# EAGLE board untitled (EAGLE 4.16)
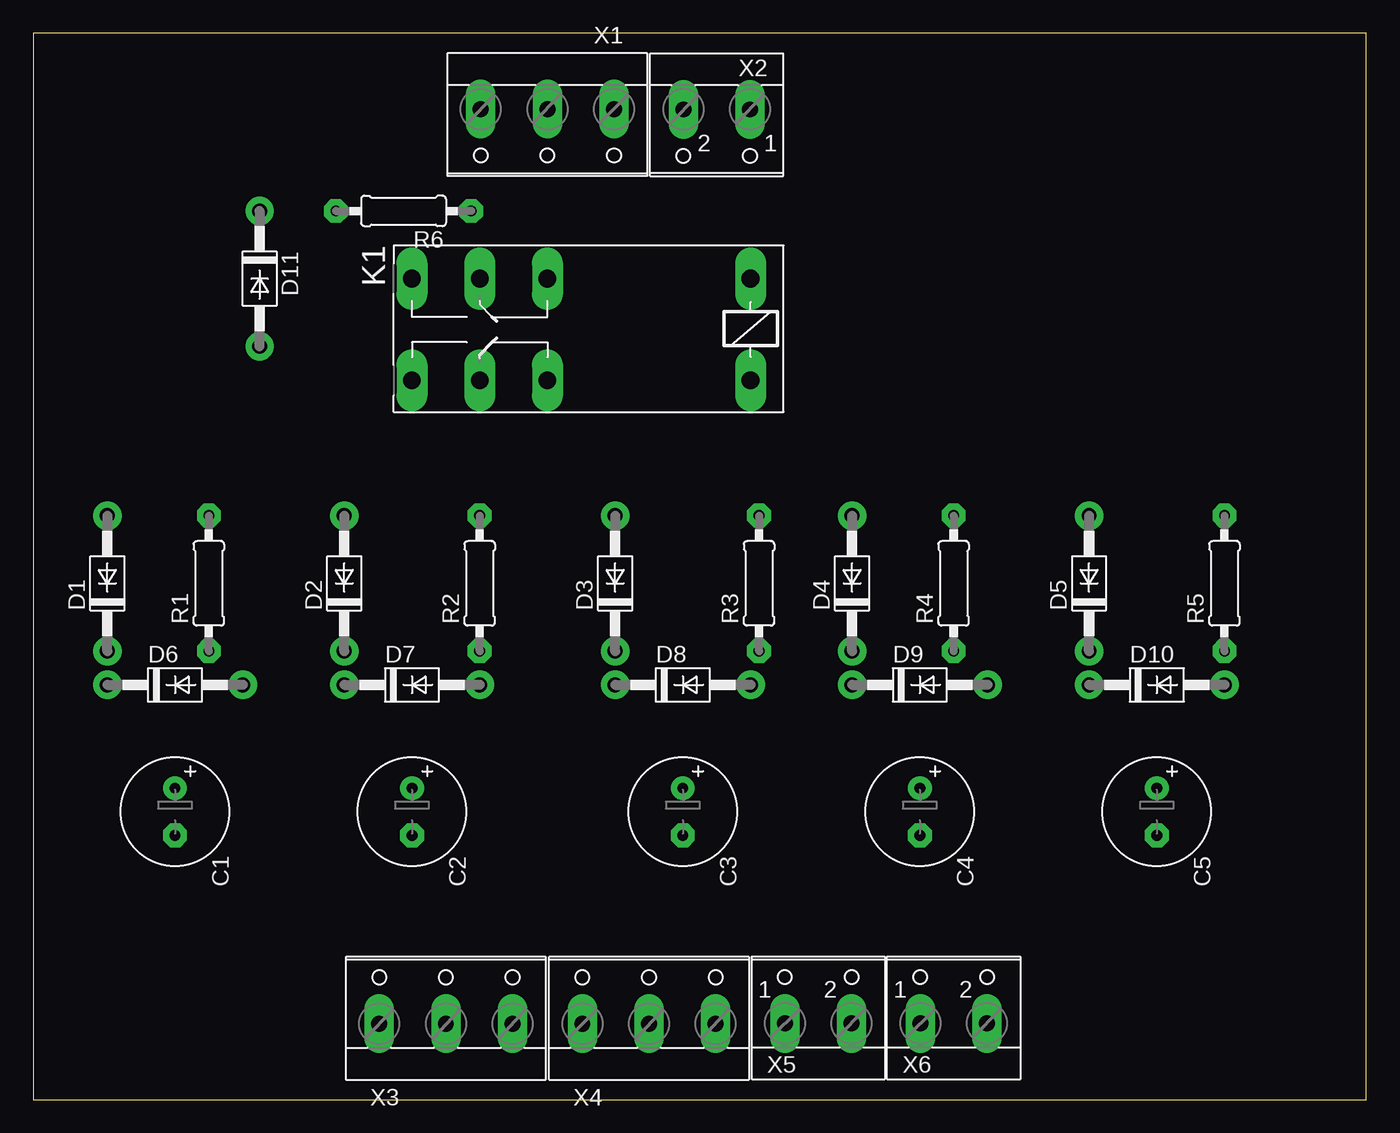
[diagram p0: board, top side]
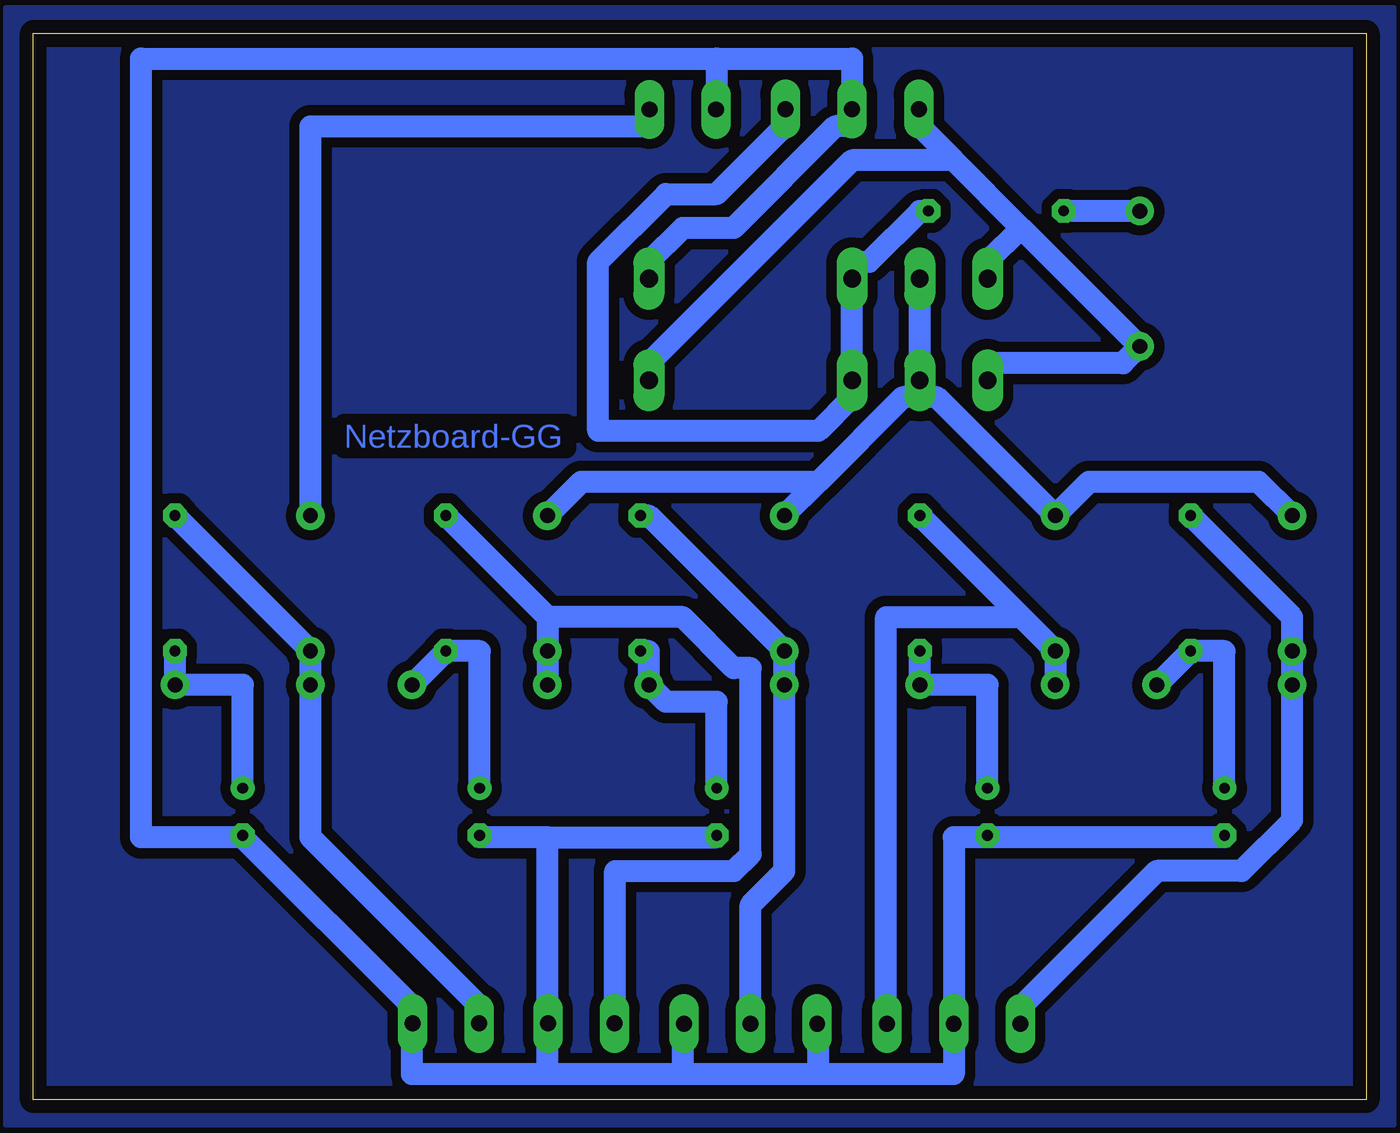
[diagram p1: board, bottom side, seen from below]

Size 100 x 80 mm. Coordinates in mm from the lower left corner, seen from the top.
Outline: 0,0 100,0 100,80 0,80 0,0
Copper layers (1*16): Top 0.035mm / dielectric 1.5mm / Bottom 0.035mm
Design rules "handyalarm0,0undmehr": minimum track width 65mil, minimum drill 24mil, track to track 30mil, track to pad 30mil, pad to pad 30mil, via to via 8mil, smd to smd 8mil, copper to edge 40mil, drill to drill 8mil, minimum pad ring 10mil, minimum via ring 8mil, stop-mask expansion 4mil, vias tented up to drill 0mil, thermal gap 10mil

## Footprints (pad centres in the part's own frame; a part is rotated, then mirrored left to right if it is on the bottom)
E3,5-8 = drill 0.813 pad 1.6 round: + -1.778,0 | drill 0.813 pad 1.6 octagon: - 1.778,0
DO41-10 = drill 1.118 round: A 5.08,0; C -5.08,0
RP420 = drill 1.321 long: 11 16.51,-3.81; 12 11.43,-3.81; 14 21.59,-3.81; 21 16.51,3.81; 22 11.43,3.81; 24 21.59,3.81; A1 -3.81,-3.81; A2 -3.81,3.81
0207/10 = drill 0.813 octagon: 1 -5.08,0; 2 5.08,0
W237-103 = drill 1.194 long: 1 -5,-1.29; 2 0,-1.29; 3 5,-1.29
W237-102 = drill 1.194 long: 1 -2.5,-1.27; 2 2.5,-1.27

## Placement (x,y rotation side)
C1  [E3,5-8]  10.63,21.58 270 top
C2  [E3,5-8]  28.41,21.58 270 top
C3  [E3,5-8]  48.73,21.58 270 top
C4  [E3,5-8]  66.51,21.58 270 top
C5  [E3,5-8]  84.29,21.58 270 top
D1  1N4004  [DO41-10]  5.55,38.73 90 top
D2  1N4004  [DO41-10]  23.33,38.73 90 top
D3  1N4004  [DO41-10]  43.65,38.73 90 top
D4  1N4004  [DO41-10]  61.43,38.73 90 top
D5  1N4004  [DO41-10]  79.21,38.73 90 top
D6  1N4004  [DO41-10]  10.63,31.11 0 top
D7  1N4004  [DO41-10]  28.41,31.11 0 top
D8  1N4004  [DO41-10]  48.73,31.11 0 top
D9  1N4004  [DO41-10]  66.51,31.11 0 top
D10  1N4004  [DO41-10]  84.29,31.11 0 top
D11  1N4004  [DO41-10]  16.98,61.59 270 top
K1  RP420024  [RP420]  50,57.78 180 top
R1  [0207/10]  13.17,38.73 90 top
R2  [0207/10]  33.49,38.73 90 top
R3  [0207/10]  54.45,38.73 90 top
R4  [0207/10]  69.05,38.73 90 top
R5  [0207/10]  89.37,38.73 90 top
R6  [0207/10]  27.77,66.67 180 top
X1  [W237-103]  38.57,73.02 180 top
X2  [W237-102]  51.27,73.02 180 top
X3  [W237-103]  30.95,6.98 0 top
X4  [W237-103]  46.19,6.98 0 top
X5  [W237-102]  58.89,6.98 0 top
X6  [W237-102]  69.05,6.98 0 top

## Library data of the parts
C1-C5 R1-R6 = rcl
D1-D11 = diode
K1 = relay
X1-X6 = con-wago-500

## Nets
N$1: D1.A D2.A D3.A D4.A K1.11 K1.21
N$2: D1.C D6.C R1.2 X3.1
N$3: D2.C D7.C R2.2 X3.3
N$4: D3.C D8.C R3.2 X4.2
N$5: D4.C D9.C R4.2 X5.1
N$6: D5.C D10.C R5.2 X6.1
N$7: C1.+ D6.A R1.1
N$8: C2.+ D7.A R2.1
N$9: C3.+ D8.A R3.1
N$10: C4.+ D9.A R4.1
N$11: C5.+ D10.A R5.1
N$12: K1.12 K1.22 R6.1 X1.1
N$14: D11.A K1.14 K1.24 K1.A2 X1.3
N$15: D5.A X2.1
N$16: C1.- C2.- C3.- C4.- C5.- K1.A1 X1.2 X2.2 X3.2 X4.1 X4.3 X5.2 X6.2
N$17: D11.C R6.2

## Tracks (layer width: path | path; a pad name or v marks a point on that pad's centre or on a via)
N$1
  Bottom 1.651: D1.A 8.09,46.35 20.79,46.35 D2.A 32.22,52.7 33.49,52.7 | 41.11,46.35 34.76,52.7 33.49,52.7 | 41.11,46.35 D3.A | D4.A 58.89,46.35 41.11,46.35 | K1.11 K1.21 33.49,52.7
N$2
  Bottom 1.651: R1.2 5.55,36.19 D1.C D6.C 5.55,20.95 9.36,17.14 15.71,17.14 25.87,6.98 X3.1
N$3
  Bottom 1.651: 25.87,36.19 D2.C D7.C | 25.87,36.19 R2.2 | 25.87,36.19 36.03,36.19 36.03,6.98 X3.3
N$4
  Bottom 1.651: R3.2 53.81,43.81 D3.C D8.C 43.65,17.14 46.19,14.6 X4.2
N$5
  Bottom 1.651: 61.43,36.19 R4.2 | 61.43,36.19 D4.C D9.C | 61.43,36.19 51.27,36.19 47.46,32.38 46.19,32.38 46.19,18.41 47.46,17.14 56.35,17.14 56.35,6.98 X5.1
N$6
  Bottom 1.651: R5.2 D5.C D10.C 79.21,19.68 66.51,6.98 X6.1
N$7
  Bottom 1.651: C1.+ 10.63,33.65 R1.1 D6.A
N$8
  Bottom 1.651: C2.+ 28.41,31.11 D7.A R2.1
N$9
  Bottom 1.651: C3.+ 48.73,29.84 52.54,29.84 D8.A 53.81,33.65 R3.1
N$10
  Bottom 1.651: C4.+ 66.51,33.65 R4.1 D9.A
N$11
  Bottom 1.651: C5.+ 84.29,31.11 D10.A R5.1
N$12
  Bottom 1.651: R6.1 33.49,66.67 37.3,62.86 38.57,62.86 K1.12 K1.22 38.57,52.7 41.11,50.16 57.62,50.16 57.62,62.86 52.54,67.94 48.73,67.94 43.65,73.02 X1.1
N$14
  Bottom 1.651: K1.24 28.41,55.24 18.25,55.24 D11.A 25.87,65.4 | 25.87,65.4 30.95,70.48 | 30.95,70.48 33.49,73.02 X1.3 | 30.95,70.48 38.57,70.48 53.81,55.24 K1.A2 | 25.87,65.4 28.41,62.86 K1.14
N$15
  Bottom 1.651: D5.A 79.21,73.02 53.81,73.02 X2.1
N$16
  Bottom 1.651: 28.41,19.68 10.63,19.68 C1.- | 28.41,19.68 30.95,19.68 X3.2 30.95,1.9 41.11,1.9 | 28.41,19.68 C2.- | 48.73,78.1 48.73,75.56 X2.2 | 48.73,78.1 38.57,78.1 X1.2 38.57,73.02 39.84,73.02 47.46,65.4 51.27,65.4 53.81,62.86 K1.A1 | 84.29,19.68 71.59,6.98 X6.2 71.59,4.44 71.59,1.9 61.43,1.9 | 41.11,1.9 41.11,4.44 X4.1 | 41.11,1.9 51.27,1.9 | 51.27,1.9 51.27,4.44 X4.3 | 61.43,19.68 66.51,19.68 C4.- | 61.43,19.68 48.73,19.68 C3.- | 61.43,19.68 61.43,6.98 X5.2 61.43,4.44 61.43,1.9 | 51.27,1.9 61.43,1.9 | 48.73,78.1 91.91,78.1 91.91,19.68 84.29,19.68 | 84.29,19.68 C5.-
N$17
  Bottom 1.651: D11.C R6.2
N$18
  pour Bottom: -2.07,81.91 102.07,81.91 102.07,-1.91 -2.07,-1.91

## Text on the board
Bottom: Netzboard-GG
